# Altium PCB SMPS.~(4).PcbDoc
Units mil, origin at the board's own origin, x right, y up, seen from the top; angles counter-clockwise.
Board outline 2362.21 x 3149.61 mil, 2 copper layers (Top Layer, Bottom Layer); 139 components, 61 nets, 421 pads, 34 vias.
Unrouted connection lines stored in the file: 287.
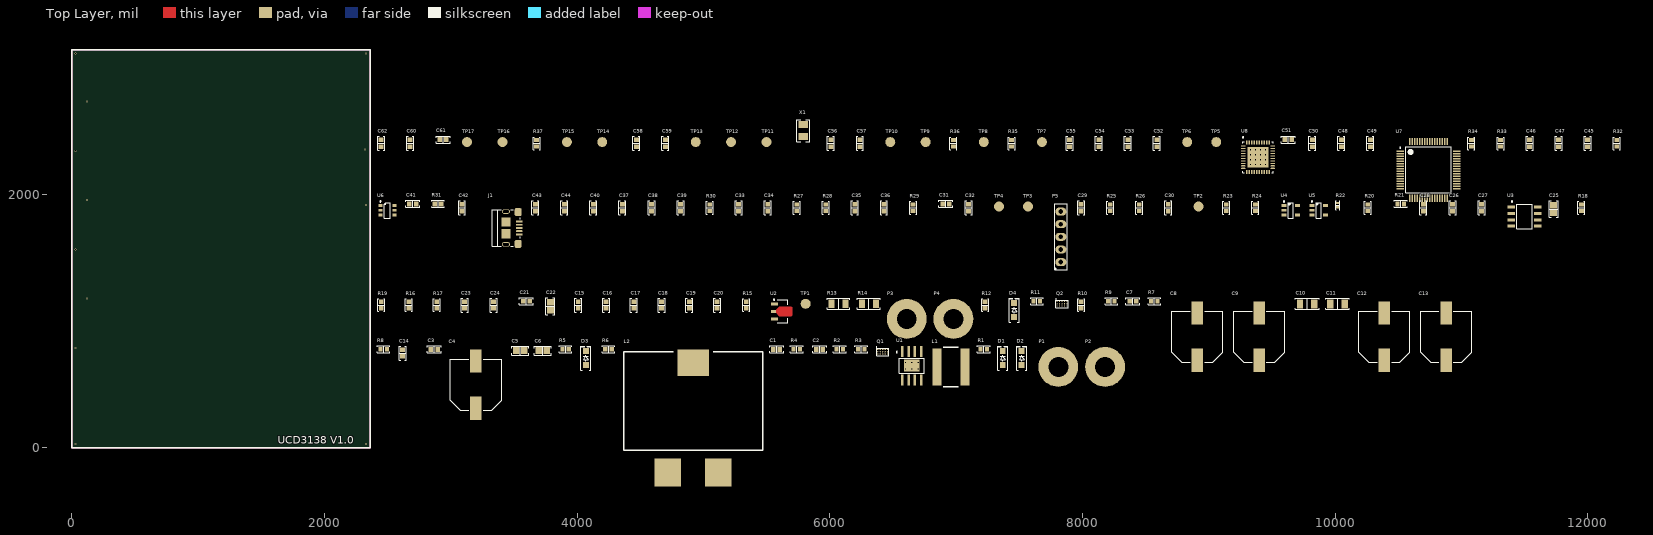
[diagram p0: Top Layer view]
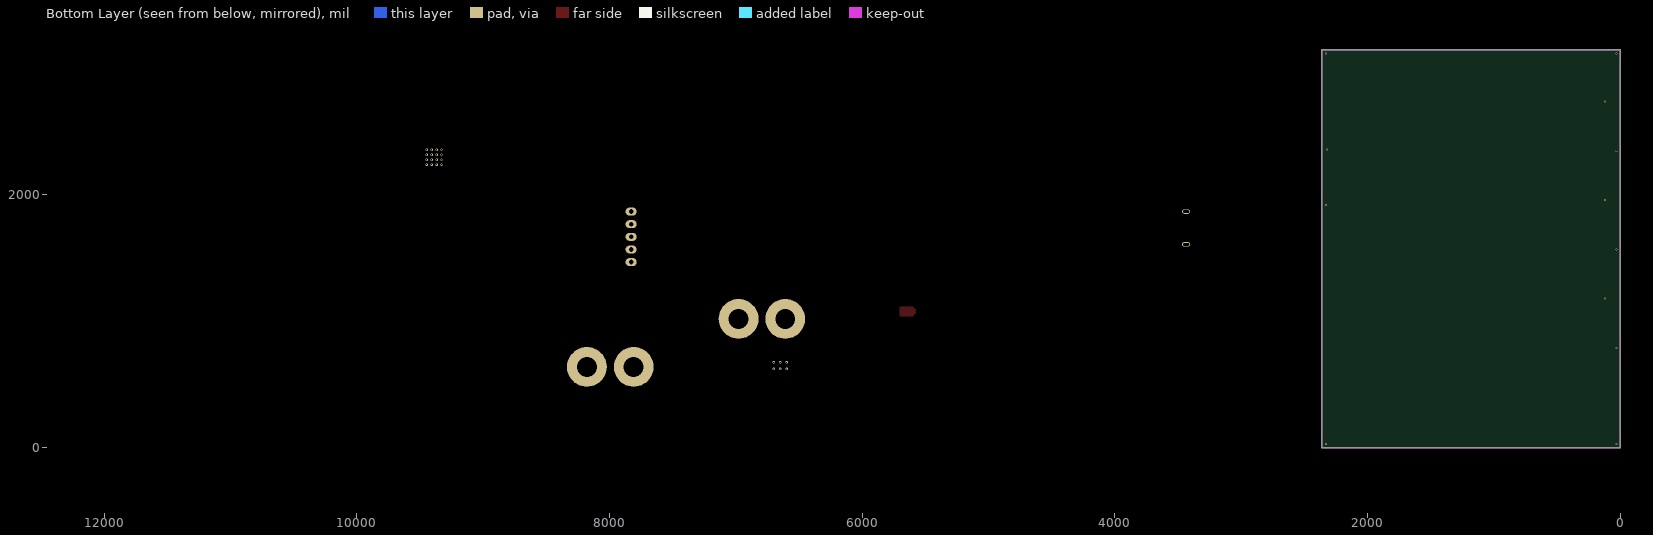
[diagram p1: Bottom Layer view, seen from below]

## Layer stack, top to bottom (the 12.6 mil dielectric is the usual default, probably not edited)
Top Solder: solder mask 0.4, Solder Resist, Dk 3.5
Top Layer: signal copper 1.4
Dielectric 1: dielectric 12.6, FR-4, Dk 4.8
Bottom Layer: signal copper 1.4
Bottom Solder: solder mask 0.4, Solder Resist, Dk 3.5

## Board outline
0,0 0,3149.61 2362.2,3149.61 2362.2,0

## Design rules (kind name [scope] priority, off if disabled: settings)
Clearance [All] p1: gap=10 ignorepadtopadclearanceinfootprint=FALSE except(0: Arc-Hole Track-Hole SMDPad-Hole THPad-Hole Via-Hole Fill-Hole Poly-Hole Region-Hole Text-Hole; 7: SMDPad-SMDPad; 8: Track-SMDPad; 9: Arc-Arc Arc-Track Arc-SMDPad Track-Track; 20: THPad-THPad)
ComponentClearance U1 [InComponent('U1')] p1: gap=20 collisioncheckmode=3 verticalgap=0 showdistances=TRUE
ComponentClearance [All] p2: gap=19.68 collisioncheckmode=3 verticalgap=3.94 showdistances=TRUE
Height [All] p1: minheight=0 maxheight=2000 prefheight=500
HoleSize [All] p1: absolutevalues=TRUE maxlimit=393.7 minlimit=7.87 maxpercent=80.000 minpercent=20.000
MinimumSolderMaskSliver [All] p1: minsoldermaskwidth=1
PlaneClearance [All] p1: clearance=10
PlaneConnect [All] p1: planeconnectstyle=Direct reliefexpansion=20 reliefentries=4 reliefconductorwidth=20 reliefairgap=20
PolygonConnect GND [InNet('GND')] p1: connectstyle=Direct reliefconductorwidth=10 reliefentries=4 polygonreliefangle="90 Angle" airgapwidth=10
PolygonConnect DirectConnect [All] p2: connectstyle=Direct reliefconductorwidth=10 reliefentries=4 polygonreliefangle="90 Angle" airgapwidth=10
RoutingVias [All] p1: holewidth=7.87 width=31.5 viastyle="Through Hole" minholewidth=7.87 minwidth=15.75 maxholewidth=15.75 maxwidth=31.5
SilkToSilkClearance [All] p1: silktosilkclearance=0
SolderMaskExpansion [All] p1: expansion=4
Width [All] p1: maxlimit=500 minlimit=10 preferedwidth=10
23 further rules are at their usual default settings.

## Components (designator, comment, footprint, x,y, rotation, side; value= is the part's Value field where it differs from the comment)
C1 "10nF" C0603 5578.9,778.9 r0 top
C2 "1nF" C0603 5918.9,778.9 r0 top
C3 "10nF" C0603 2868.9,778.9 r0 top
C4 "47µF 80V" "CAP ALUM 10.3MM" 3198.9,498.9 r90 top
C5 "10µF 16V" C0805 3548.9,768.9 r0 top
C6 "10µF 16V" C0805 3728.9,768.9 r0 top
C7 "10nF" C0603 8398.9,1158.9 r0 top
C8 "47µF 80V" "CAP ALUM 10.3MM" 8908.9,878.9 r90 top
C9 "47µF 80V" "CAP ALUM 10.3MM" 9398.9,878.9 r90 top
C10 "1µF 80V" C1206 9778.9,1138.9 r0 top
C11 "1µF 80V" C1206 10018.9,1138.9 r0 top
C12 "47µF 80V" "CAP ALUM 10.3MM" 10388.9,878.9 r90 top
C13 "47µF 80V" "CAP ALUM 10.3MM" 10878.9,878.9 r90 top
C14 "47pF" C0603 2618.9,748.9 r90 top
C15 "10µF" C0603 4008.9,1128.9 r90 top
C16 "100nF" C0603 4228.9,1128.9 r90 top
C17 "10nF" C0603 4448.9,1128.9 r90 top
C18 "10µF" C0603 4668.9,1128.9 r90 top
C19 "100nF" C0603 4888.9,1128.9 r90 top
C20 "10nF" C0603 5108.9,1128.9 r90 top
C21 "100nF 16V" C0603 3598.9,1158.9 r0 top
C22 "1µF 16V" C0805 3788.9,1118.9 r90 top
C23 "22pF" C0603 3108.9,1128.9 r90 top
C24 "22pF" C0603 3338.9,1128.9 r90 top
C25 "10µF 16V" C0805 11728.9,1888.9 r90 top
C26 "33pF" C0603 10928.9,1898.9 r90 top
C27 "33pF" C0603 11158.9,1898.9 r90 top
C28 "1µF 16V" C0603 10698.9,1898.9 r90 top
C29 "22pF" C0603 7988.9,1898.9 r90 top
C30 "22pF" C0603 8678.9,1898.9 r90 top
C31 "1µF" C0603 6918.9,1928.9 r0 top
C32 "1µF" C0603 7098.9,1898.9 r90 top
C33 "100nF" C0603 5278.9,1898.9 r90 top
C34 "22pF" C0603 5508.9,1898.9 r90 top
C35 "22pF" C0603 6198.9,1898.9 r90 top
C36 "100nF" C0603 6428.9,1898.9 r90 top
C37 "4.7µF" C0603 4358.9,1898.9 r90 top
C38 "4.7µF" C0603 4588.9,1898.9 r90 top
C39 "4.7µF" C0603 4818.9,1898.9 r90 top
C40 "47pF" C0603 4128.9,1898.9 r90 top
C41 "10nF" C0603 2698.9,1928.9 r0 top
C42 "10nF" C0603 3088.9,1898.9 r90 top
C43 "100nF" C0603 3668.9,1898.9 r90 top
C44 "100nF" C0603 3898.9,1898.9 r90 top
C45 "1µF" C0603 11998.9,2408.9 r90 top
C46 "10nF" C0603 11538.9,2408.9 r90 top
C47 "100nF" C0603 11768.9,2408.9 r90 top
C48 "2.2µF" C0603 10048.9,2408.9 r90 top
C49 "10nF" C0603 10278.9,2408.9 r90 top
C50 "47pF" C0603 9818.9,2408.9 r90 top
C51 "100nF" C0603 9628.9,2438.9 r0 top
C52 "1nF" C0603 8588.9,2408.9 r90 top
C53 "100nF" C0603 8358.9,2408.9 r90 top
C54 "1nF" C0603 8128.9,2408.9 r90 top
C55 "100nF" C0603 7898.9,2408.9 r90 top
C56 "33pF" C0603 6008.9,2408.9 r90 top
C57 "33pF" C0603 6238.9,2408.9 r90 top
C58 "26pF" C0603 4468.9,2408.9 r90 top
C59 "26pF" C0603 4698.9,2408.9 r90 top
C60 "2.2µF" C0603 2678.9,2408.9 r90 top
C61 "1µF" C0603 2938.9,2438.9 r0 top
C62 "1µF" C0603 2448.9,2408.9 r90 top
D1 "DSS120UTR" SOD123F 7368.9,708.9 r90 top
D2 "DSS120UTR" SOD123F 7518.9,708.9 r90 top
D3 "DSS120UTR" SOD123F 4068.9,708.9 r90 top
D4 "DSS120UTR" SOD123F 7458.9,1088.9 r90 top
J1 "10118192-0001LF" "FCI USB 10118193-0001LF" 3438.9,1738.9 r90 top
L1 "NR8040T220M" SELF_SMD_8x8 6958.9,638.9 r0 top
L2 "PQ2617BHA-220K" SELF_SMD_PQ2617 4918.9,368.9 r0 top
P1 "PTH" HOLE_4 7808.9,638.9 r0 top
P2 "PTH" HOLE_4 8178.9,638.9 r0 top
P3 "PTH" HOLE_4 6608.9,1018.9 r0 top
P4 "PTH" HOLE_4 6978.9,1018.9 r0 top
P5 "5x2.54" "SAMTEC SSW-105-03-T-S" 7828.9,1668.9 r90 top
Q1 "EPC2045" EPC2045 6418.9,758.9 r0 top
Q2 "EPC2045" EPC2045 7838.9,1138.9 r0 top
R1 "5R11" R0603 7218.9,778.9 r0 top
R2 "21.5k 0.1%" R0603 6078.9,778.9 r0 top
R3 "21.5k 0.1%" R0603 6248.9,778.9 r0 top
R4 "249k" R0603 5738.9,778.9 r0 top
R5 "10k" R0603 3908.9,778.9 r0 top
R6 "91k" R0603 4248.9,778.9 r0 top
R7 "1k 0.1%" R0603 8568.9,1158.9 r0 top
R8 "1k 0.1%" R0603 2468.9,778.9 r0 top
R9 "5R11" R0603 8228.9,1158.9 r0 top
R10 "30.1k" R0603 7988.9,1128.9 r90 top
R11 "10k" R0603 7638.9,1158.9 r0 top
R12 "10k" R0603 7228.9,1128.9 r90 top
R13 "1m 1% 1W 50ppm" R1206 6068.9,1138.9 r0 top
R14 "1m 1% 1W 50ppm" R1206 6308.9,1138.9 r0 top
R15 "1R" R0603 5338.9,1128.9 r90 top
R16 "1k" R0603 2668.9,1128.9 r90 top
R17 "1k" R0603 2888.9,1128.9 r90 top
R18 "301k 0.1%" R0603 11948.9,1898.9 r90 top
R19 "301k 0.1%" R0603 2448.9,1128.9 r90 top
R20 "1k 0.1%" R0603 10258.9,1898.9 r90 top
R21 "1k 0.1%" R0603 10518.9,1928.9 r0 top
R22 "10k CTN" "NTC 0402/1005" 10018.9,1918.9 r90 top
R23 "1k" R0603 9138.9,1898.9 r90 top
R24 "1k" R0603 9368.9,1898.9 r90 top
R25 "1k 0.1%" R0603 8218.9,1898.9 r90 top
R26 "1k 0.1%" R0603 8448.9,1898.9 r90 top
R27 "301k 0.1%" R0603 5738.9,1898.9 r90 top
R28 "301k 0.1%" R0603 5968.9,1898.9 r90 top
R29 "10k" R0603 6658.9,1898.9 r90 top
R30 "27R" R0603 5048.9,1898.9 r90 top
R31 "1R" R0603 2898.9,1928.9 r0 top
R32 "10k" R0603 12228.9,2408.9 r90 top
R33 "1M" R0603 11308.9,2408.9 r90 top
R34 "27R" R0603 11078.9,2408.9 r90 top
R35 "100" R0603 7438.9,2408.9 r90 top
R36 "100" R0603 6978.9,2408.9 r90 top
R37 "2.2k" R0603 3678.9,2408.9 r90 top
TP1 "Test Point" "Test Point" 5808.9,1138.9 r0 top
TP2 "Test Point" "Test Point" 8918.9,1908.9 r0 top
TP3 "Test Point" "Test Point" 7568.9,1908.9 r0 top
TP4 "Test Point" "Test Point" 7338.9,1908.9 r0 top
TP5 "Test Point" "Test Point" 9058.9,2418.9 r0 top
TP6 "Test Point" "Test Point" 8828.9,2418.9 r0 top
TP7 "Test Point" "Test Point" 7678.9,2418.9 r0 top
TP8 "Test Point" "Test Point" 7218.9,2418.9 r0 top
TP9 "Test Point" "Test Point" 6758.9,2418.9 r0 top
TP10 "Test Point" "Test Point" 6478.9,2418.9 r90 top
TP11 "Test Point" "Test Point" 5498.9,2418.9 r90 top
TP12 "Test Point" "Test Point" 5218.9,2418.9 r90 top
TP13 "Test Point" "Test Point" 4938.9,2418.9 r90 top
TP14 "Test Point" "Test Point" 4198.9,2418.9 r90 top
TP15 "Test Point" "Test Point" 3918.9,2418.9 r90 top
TP16 "Test Point" "Test Point" 3408.9,2418.9 r90 top
TP17 "Test Point" "Test Point" 3128.9,2418.9 r90 top
U1 "LM5164" R-PDSO-G8 6648.9,648.9 r0 top
U2 "AP7381-33Y-13" "ON SEMI SOT-89 H" 5618.9,1078.9 r0 top
U3 "MIC4605-1YM" SOIC-8 11498.9,1828.9 r0 top
U4 "LMV793" "TI SOT-23-5 DBV" 9648.9,1878.9 r0 top
U5 "LMV793" "TI SOT-23-5 DBV" 9868.9,1878.9 r0 top
U6 "IP4234CZ6" "VISHAY TSOP-6 MO-193C" 2498.9,1878.9 r0 top
U7 "ATSAME51J20A" TQFP-64N 10738.9,2198.9 r0 top
U8 "UCD3138RHAR" S-PVQFN-N40 9388.9,2298.9 r0 top
X1 "32.768kHz" "ABRACON ABS07" 5790,2510 r90 top

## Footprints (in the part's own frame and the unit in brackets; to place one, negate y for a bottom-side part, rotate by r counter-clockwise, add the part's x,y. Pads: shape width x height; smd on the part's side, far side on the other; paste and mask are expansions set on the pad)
"ABRACON ABS07" [mm] "Crystal, 2-Leads, Body 3.20x1.50mm, IPC Medium Density"
  rect 1.4x1.9 smd: 1(-1.2,0) 2(1.2,0)
  silkscreen extent -2.2,-1.3 2.2,1.3, body extent -1.62,-0.77 1.63,0.78, height 0.9
C0603 [mm] "Chip Capacitor, 2-Leads, Body 1.60x0.80mm, IPC Medium Density"
  rect 0.9x1 smd: 1(-0.675,0) 2(0.675,0)
  silkscreen extent -1.4,-0.7 1.4,0.7, body extent -0.8,-0.41 0.8,0.41, height 0.82
C0805 [mm] "Chip Capacitor, 2-Leads, Body 2.00x1.20mm, IPC Medium Density"
  rect 1.3x1.4 smd: 1(-0.8,0) 2(0.8,0)
  silkscreen extent -1.7,-0.9 1.7,0.9, body extent -1,-0.64 1,0.64, height 1.26
C1206 [mm] "Chip Capacitor, 2-Leads, Body 3.25x1.60mm, IPC Medium Density"
  rect 1.3x1.8 smd: 1(-1.45,0) 2(1.45,0)
  silkscreen extent -2.37,-1.12 2.37,1.12, body extent -1.6,-0.81 1.6,0.81, height 1.62
"CAP ALUM 10.3MM" [mm] "Aluminum Electrolytic Capacitor, Body 10.30x10.30x10.50mm, IPC Low Density"
  rect 4.65x2.3 smd: 1(-4.75,0) 2(4.75,0)
  silkscreen extent -5.15,-5.15 5.15,5.15, body extent -5.8,-5.15 5.8,5.15, height 10.5
EPC2045 [mm] "EPC2045 GaNFet"
  round 0.23 smd: 1(-1,0.45) 2(-1,0) 3(-1,-0.45) 4(-0.5,0.45) 5(-0.5,0) 6(-0.5,-0.45) 7(0,0.45) 8(0,0) 9(0,-0.45) 10(0.5,0.45) 11(0.5,0) 12(0.5,-0.45) 13(1,0.45) 14(1,0) 15(1,-0.45)
  silkscreen extent -1.3,-0.75 1.25,1.05, body extent -1.25,-0.75 1.25,0.75, height 0.68
"FCI USB 10118193-0001LF" [mm] "USB 2.0 Type B Micro"
  oval 0.4x1.35 smd: 1(1.3,-2.625) 2(0.65,-2.625) 3(0,-2.625) 4(-0.65,-2.625) 5(-1.3,-2.625)
  oval 0.9x1.6 hole 0.5 slot 1.2 at 90 deg: S(-3.3,0.05) S(3.3,0.05)
  rrect50% 1.6x1.4 smd: S(-3.2,-2.4) S(3.2,-2.4)
  rect 1.9x1.8 smd: S(-1.2,0.05) S(1.2,0.05)
  silkscreen extent -3.7,-2.8 3.7,2.8, body extent -3.93,-2.9 3.93,2.76, height 2.78
HOLE_4 [mm] "Hole for M4 screw"
  round 8 hole 4: 1(0,0)
"NTC 0402/1005" [mm] "Chip Thermistor, 2-Leads, Body 1.00x0.50mm, IPC Medium Density"
  rect 0.5x0.55 smd: 1(-0.45,0) 2(0.45,0)
  silkscreen extent -0.9,-0.4 0.9,0.4, body extent -0.5,-0.26 0.5,0.26, height 0.52
"ON SEMI SOT-89 H" [mm] "SOT89, 3-Leads, Body 4.50x2.50mm, Pitch 1.50mm, Lead Span 3.3mm, IPC Medium Density"
  rect 1.4x0.6 smd: 1(-1.4,1.5) 3(-1.4,-1.5)
  rect 1x0.6 smd: 2(-1.6,0)
  Top Layer region: -1.1,0.3 -0.45,0.95 1.975,0.95 2.1,0.825 2.1,-0.825 1.975,-0.95 -0.45,-0.95 -1.1,-0.3
  silkscreen extent -1.65,-2.3 1.25,2.47, body extent -2.05,-2.25 2.1,2.25, height 1.5
R0603 [mm] "Chip Resistor, 2-Leads, Body 1.60x0.80mm, IPC Medium Density"
  rect 0.85x0.95 smd: 1(-0.65,0) 2(0.65,0)
  silkscreen extent -1.27,-0.7 1.27,0.7, body extent -0.8,-0.4 0.8,0.4, height 0.45
R1206 [mm] "Chip Resistor, 2-Leads, Body 3.13x1.55mm, IPC Medium Density"
  rect 1.2x1.65 smd: 1(-1.4,0) 2(1.4,0)
  silkscreen extent -2.3,-1.1 2.3,1.1, body extent -1.57,-0.8 1.62,0.8, height 0.6
R-PDSO-G8 [mm] "SOIC, 8-Leads, Body 4,90x3,90mm, Pitch 1,27mm, Thermal Pad 3,10x2,40mm, IPC Medium Density"
  rect 0.5x2.2 smd: 1(-1.905,2.875) 2(-0.635,2.875) 3(0.635,2.875) 4(1.905,2.875) 5(1.905,-2.875) 6(0.635,-2.875) 7(-0.635,-2.875) 8(-1.905,-2.875)
  rect 3.1x2.4 smd paste+0: 9(0,0)
  silkscreen extent -3.12,-1.52 2.5,2.87, body extent -2.5,-2 2.5,2, height 1.7
S-PVQFN-N40 [mm] "VQFN, 40-Leads, Body 6,00x6,00mm, Pitch 0,50mm, Thermal Pad 4,92x4,92mm, IPC Medium Density"
  oval 0.85x0.28 smd: 1(-2.975,2.25) 2(-2.975,1.75) 3(-2.975,1.25) 4(-2.975,0.75) 5(-2.975,0.25) 6(-2.975,-0.25) 7(-2.975,-0.75) 8(-2.975,-1.25) 9(-2.975,-1.75) 10(-2.975,-2.25) 21(2.975,-2.25) 22(2.975,-1.75) 23(2.975,-1.25) 24(2.975,-0.75) 25(2.975,-0.25) 26(2.975,0.25) 27(2.975,0.75) 28(2.975,1.25) 29(2.975,1.75) 30(2.975,2.25)
  oval 0.28x0.85 smd: 11(-2.25,-2.975) 12(-1.75,-2.975) 13(-1.25,-2.975) 14(-0.75,-2.975) 15(-0.25,-2.975) 16(0.25,-2.975) 17(0.75,-2.975) 18(1.25,-2.975) 19(1.75,-2.975) 20(2.25,-2.975) 31(2.25,2.975) 32(1.75,2.975) 33(1.25,2.975) 34(0.75,2.975) 35(0.25,2.975) 36(-0.25,2.975) 37(-0.75,2.975) 38(-1.25,2.975) 39(-1.75,2.975) 40(-2.25,2.975)
  rect 4.15x4.15 smd paste-2.075: 41(0,0)
  silkscreen extent -3.12,-3.08 3.08,4.12, body extent -3.08,-3.08 3.08,3.08, height 1
"SAMTEC SSW-105-03-T-S" [mm]
  oval 1.6x2.25 hole 0.95: 1(-5.08,0) 2(-2.54,0) 3(0,0) 4(2.54,0) 5(5.08,0)
  silkscreen extent -6.61,-1.27 6.61,1.27, body extent -6.6,-1.21 6.6,1.21, height 8.51
SELF_SMD_8x8 [mm] "Self SMD 8x8mm"
  rect 1.8x7.5 smd: 1(-2.8,0) 2(2.8,0)
  silkscreen extent -1.5,-4 1.5,4, body extent -4,-4 4,4, height 3
SELF_SMD_PQ2617 [mil] "Bourns shielded power inductor PQ2617"
  rect 210x220 smd: 1(-200,-565) 2(200,-565)
  rect 250x208 smd: 3(0,304)
  silkscreen extent -549,-390 549,390, body extent -549,-433 549,433, height 748
SOD123F [mm] "SODFL, 2-Leads, Body 1.60x3.50mm, IPC Medium Density"
  rect 1.2x1.2 smd: 1(-1.43,0) 2(1.43,0)
  silkscreen extent -2.41,-1.02 2.41,1.02, body extent -1.75,-0.8 1.75,0.8, height 1.1
SOIC-8 [mm] "8-Pin Plastic Narrow Body Small Outline Integrated Circuit 1.27 mm Pitch, IPC Medium Density"
  rect 1.5x0.6 smd: 1(-2.7,1.905) 2(-2.7,0.635) 3(-2.7,-0.635) 4(-2.7,-1.905) 5(2.7,-1.905) 6(2.7,-0.635) 7(2.7,0.635) 8(2.7,1.905)
  silkscreen extent -2.66,-2.45 1.52,3.17, body extent -1.95,-2.45 1.95,2.45, height 1.76
"Test Point" [mm] "Test Point"
  round 2 smd: 1(0,0)
"TI SOT-23-5 DBV" [mm] "SOT23, 5-Leads, Body 2.90x2.80mm, Pitch 0.95mm, IPC Medium Density"
  rect 1x0.55 smd: 1(-1.35,0.95) 2(-1.35,0) 3(-1.35,-0.95) 4(1.35,-0.95) 5(1.35,0.95)
  silkscreen extent -1.47,-1.55 0.5,1.9, body extent -1.44,-1.43 1.39,1.48, height 1.5
TQFP-64N [mm] "TSQFP, 64-Leads, Body 10,00x10,00mm, Pitch 0,50mm, IPC Medium Density"
  rect 1.5x0.3 smd: 1(-5.7,3.75) 2(-5.7,3.25) 3(-5.7,2.75) 4(-5.7,2.25) 5(-5.7,1.75) 6(-5.7,1.25) 7(-5.7,0.75) 8(-5.7,0.25) 9(-5.7,-0.25) 10(-5.7,-0.75) 11(-5.7,-1.25) 12(-5.7,-1.75) 13(-5.7,-2.25) 14(-5.7,-2.75) 15(-5.7,-3.25) 16(-5.7,-3.75) 33(5.7,-3.75) 34(5.7,-3.25) 35(5.7,-2.75) 36(5.7,-2.25) 37(5.7,-1.75) 38(5.7,-1.25) 39(5.7,-0.75) 40(5.7,-0.25) 41(5.7,0.25) 42(5.7,0.75) 43(5.7,1.25) 44(5.7,1.75) 45(5.7,2.25) 46(5.7,2.75) 47(5.7,3.25) 48(5.7,3.75)
  rect 0.3x1.5 smd: 17(-3.75,-5.7) 18(-3.25,-5.7) 19(-2.75,-5.7) 20(-2.25,-5.7) 21(-1.75,-5.7) 22(-1.25,-5.7) 23(-0.75,-5.7) 24(-0.25,-5.7) 25(0.25,-5.7) 26(0.75,-5.7) 27(1.25,-5.7) 28(1.75,-5.7) 29(2.25,-5.7) 30(2.75,-5.7) 31(3.25,-5.7) 32(3.75,-5.7) 49(3.75,5.7) 50(3.25,5.7) 51(2.75,5.7) 52(2.25,5.7) 53(1.75,5.7) 54(1.25,5.7) 55(0.75,5.7) 56(0.25,5.7) 57(-0.25,5.7) 58(-0.75,5.7) 59(-1.25,5.7) 60(-1.75,5.7) 61(-2.25,5.7) 62(-2.75,5.7) 63(-3.25,5.7) 64(-3.75,5.7)
  silkscreen extent -5.82,-4.6 4.6,4.6, body extent -5,-5 5,5, height 1.2
"VISHAY TSOP-6 MO-193C" [mm] "SOT23, 6-Leads, Body 3.03x2.84mm, Pitch 0.95mm, IPC Medium Density"
  rect 0.85x0.55 smd: 1(-1.425,0.95) 2(-1.425,0) 3(-1.425,-0.95) 4(1.425,-0.95) 5(1.425,0) 6(1.425,0.95)
  silkscreen extent -1.55,-1.55 0.6,1.9, body extent -1.44,-1.52 1.44,1.53, height 1.45

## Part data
C1 C2 C3 C4 C5 C6 C7 C8 C9 C10 C11 C12 C13 C14 C15 C16 C17 C18 C19 C20 C21 C22 C23 C24 C25 C26 C27 C28 C29 C30 C31 C32 C33 C34 C35 C36 C37 C38 C39 C40 C41 C42 C43 C44 C45 C46 C47 C48 C49 C50 C51 C52 C53 C54 C55 C56 C57 C58 C59 C60 C61 C62: library part Cap, "Capacitor"
D1 D2 D3 D4: library part "D Schottky", "Schottky Diode"
J1: library part 1-353576-1, "USB 1.1, Right Angle, SMT, A Type, Receptacle, 4 Position, White"
L1 L2: library part "Inductor Iron", "Magnetic-Core Inductor"
P1 P2 P3 P4: "Plated Trough Hole for screew"
P5: library part "Header 5", "Header, 5-Pin"
Q1 Q2: library part MOSFET_N
R1 R2 R3 R4 R5 R6 R7 R8 R9 R10 R11 R12 R13 R14 R15 R16 R17 R18 R19 R20 R21 R23 R24 R25 R26 R27 R28 R29 R30 R31 R32 R33 R34 R35 R36 R37: library part Res2, "Resistor"
R22: library part "Res Varistor", "Varistor (Voltage-Sensitive Resistor)"
U1: "100-V Input, 1-A synchronous buck DC/DC converter with ultra-low IQ"
U2: library part "Volt Reg", "Voltage Regulator"
U3: "85V Half-Bridge MOSFET Driver with Adaptive Dead Time  and Shoot-Through Protection"
U4 U5: library part "AOP - 1"
U6: "Single USB 2.0 ESD protection to IEC 61000-4-2 level 4"
U8: "Highly Integrated Digital Controller for Isolated Power with 3 Feedback Loops and 8 DPWM Outputs, 40pins"
X1: library part XTAL, "Crystal Oscillator"

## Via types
v1: diameter 19.68, hole 7.87, Top Layer to Bottom Layer, 22 vias
v2: diameter 15.75, hole 7.87, Top Layer to Bottom Layer, 12 vias

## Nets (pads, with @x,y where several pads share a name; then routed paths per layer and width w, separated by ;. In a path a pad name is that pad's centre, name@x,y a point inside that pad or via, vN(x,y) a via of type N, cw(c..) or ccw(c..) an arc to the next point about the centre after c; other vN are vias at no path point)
+3.3V: C15.1 C16.1 C17.1 C38.1 C42.1 C43.2 C48.2 C51.2 C53.1 C55.2 C62.2 P5.1 R15.2 R31.1 R32.2 U2.1 U7.8 U7.21 U7.34 U7.48 U7.56 U8.27
+3.3Vana: C18.1 C19.1 C20.1 C33.1 C36.1 R15.1 R22.2 TP1.1 U4.5 U5.5
+12V: C2.2 C5.1 C6.1 C21.1 C22.1 C25.2 L1.2 R6.1 U3.1
+Vbus: C8.2 C9.2 C10.2 D1.1 L2.1 P1.1 R2.1
+Vcells: C11.2 C12.2 C13.2 D2.1 P2.1 Q1.3 R3.1
ALERT: TP9.1 U7.19 U8.19
Ccells: C28.1 L2.2 Q1.2 Q2.3 R5.2 TP3.1 U3.4
CTRL: TP10.1 U7.20 U8.20
DPWM0A: TP5.1 U3.5 U8.11
DPWM0B: TP6.1 U3.6 U8.12
GND: C4.1 C5.2 C6.2 C8.1 C9.1 C10.1 C11.1 C12.1 C13.1 C15.2 C16.2 C17.2 C18.2 C19.2 C20.2 C21.2 C22.2 C25.1 C26.1 C27.1 C31.1 C32.1 C33.2 C34.1 C35.1 C36.2 C37.1 C38.2 C39.2 C40.1 C41.1 C42.2 C43.1 C44.2 C45.1 C46.2 C47.1 C49.1 C50.1 C51.1 C52.2 C53.2 C54.2 C55.1 C56.2 C57.2 C58.1 C59.1 C60.2 C61.2 C62.1 J1.5 P5.5 Q2.2 R10.2 R11.2 R12.2 R13.1 R14.2 R25.1 R26.2 R27.2 R28.2 R29.2 R33.1 U1.1 U1.9 U2.2 U3.7 U4.2 U5.2 U7.7 U7.22 U7.33 U7.47 U7.54 U8.1 U8.6 U8.26 U8.29 U8.30 U8.32 U8.34 U8.36 U8.41
  other v1: 6597.72,623.31 6648.9,623.31 6700.08,623.31 6597.72,674.49 6648.9,674.49 6700.08,674.49 9329.84,2239.84 9369.21,2239.84 9408.58,2239.84 9447.95,2239.84 9329.84,2279.21 9369.21,2279.21 9408.58,2279.21 9447.95,2279.21 9329.84,2318.58 9369.21,2318.58 9408.58,2318.58 9447.95,2318.58 9329.84,2357.95 9369.21,2357.95 9408.58,2357.95 9447.95,2357.95
  other v2: 30,30 2330,30 30,790 120,1180 30,1570 2330,1920 120,1960 30,2350 2320,2360 120,2740 30,3120 2330,3120
Hcells: D3.2 R1.1 TP2.1 U3.3
Ibus_peak: C26.2 R16.2 TP13.1 U8.40
Ibus_sense: C31.2 R23.2 TP12.1 U8.39
Icells_peak: C27.2 R17.1 TP16.1 U8.3
Icells_sense: C32.2 R24.1 TP15.1 U8.4 U8.35
Lcells: D4.2 R9.1 TP4.1 U3.8
NetC1_1: C1.1 L1.1 R4.1 U1.8
NetC1_2: C1.2 U1.7
NetC2_1: C2.1 C14.2 R4.2
NetC4_2: C4.2 D1.2 D2.2 U1.2 U1.3
NetC14_1: C14.1 R6.2 R11.1 U1.5
NetC23_1: C23.1 R16.1 R18.2 R23.1 U4.1
NetC23_2: C23.2 C29.2 R18.1 R20.2 U4.4
NetC24_1: C24.1 C30.2 R19.2 R21.1 U5.4
NetC24_2: C24.2 R17.2 R19.1 R24.2 U5.1
NetC28_2: C28.2 U3.2
NetC29_1: C29.1 C34.2 R25.2 R27.1 U4.3
NetC30_1: C30.1 C35.2 R26.1 R28.1 U5.3
NetC37_2: C37.2 C41.2 R31.2 U8.37
NetC39_1: C39.1 C44.1 U7.53
NetC40_2: C40.2 R30.2 U6.6
NetC45_2: C45.2 C48.1 C49.2 U8.28
NetC46_1: C46.1 J1.S R33.2 U6.2
NetC50_2: C50.2 R34.2 U6.1
NetC56_1: C56.1 R35.1 U8.9
NetC57_1: C57.1 R36.1 U8.10
NetC58_2: C58.2 U7.31 X1.1
NetC59_2: C59.2 U7.32 X1.2
NetC60_1: C60.1 R37.1 U8.7
NetD3_1: D3.1 Q1.1 R1.2 R5.1
NetD4_1: D4.1 Q2.1 R9.2 R12.1
NetJ1_1: J1.1 U6.5
NetJ1_2: J1.2 U6.4
NetJ1_3: J1.3 U6.3
NetR10_1: R10.1 U1.4
R\S\T\: C47.2 P5.4 R32.1 U7.52
Rbus: C7.1 P3.1 R7.2 R13.2 R20.1
Rcells: C3.1 P4.1 R8.2 R14.1 R21.2
SCL: R35.2 TP7.1 U7.18
SDA: R36.2 TP8.1 U7.17
SMPS_R\E\S\E\T\: C61.1 R37.2 U7.16
SWCLK: U7.59
SWDCLK: P5.3
SWDIO: P5.2 U7.60
SYNC: U8.8
Temp: R22.1 R29.1 TP17.1 U8.2
"USB D+": R34.1 U7.46
"USB D-": R30.1 U7.45
Vbus_sense: C7.2 C52.1 R2.2 R7.1 TP11.1 U8.31 U8.38
Vcells_sense: C3.2 C54.1 R3.2 R8.1 TP14.1 U8.5 U8.33
pads on no net: J1.4 L2.3 Q1.4 Q1.5 Q1.6 Q1.7 Q1.8 Q1.9 Q1.10 Q1.11 Q1.12 Q1.13 Q1.14 Q1.15 Q2.4 Q2.5 Q2.6 Q2.7 Q2.8 Q2.9 Q2.10 Q2.11 Q2.12 Q2.13 Q2.14 Q2.15 U1.6 U2.3 U7.1 U7.2 U7.3 U7.4 U7.5 U7.6 U7.9 U7.10 U7.11 U7.12 U7.13 U7.14 U7.15 U7.23 U7.24 U7.25 U7.26 U7.27 U7.28 U7.29 U7.30 U7.35 U7.36 U7.37 U7.38 U7.39 U7.40 U7.41 U7.42 U7.43 U7.44 U7.49 U7.50 U7.51 U7.55 U7.57 U7.58 U7.61 U7.62 U7.63 U7.64 U8.13 U8.14 U8.15 U8.16 U8.17 U8.18 U8.21 U8.22 U8.23 U8.24 U8.25

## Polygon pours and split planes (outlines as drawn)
GND on Bottom Layer "GND_bottom" (solid, shelved, pour order 72): 0,0 2362.2,0 2362.2,3149.61 0,3149.61
GND on Top Layer "GND_top" (solid, shelved, pour order 73): 0,0 2362.2,0 2362.2,3149.61 0,3149.61

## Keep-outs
Keep-Out Layer:
  the board outline again, w10

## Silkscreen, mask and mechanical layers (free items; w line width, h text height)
Top Overlay:
  the board outline again, w10
  text "UCD3138 V1.0" at 1630,30 h60
Drill Drawing:
  the board outline again, w10

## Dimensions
0,-39.37 to 2362.2,-39.37 on Mechanical 2
-39.37,0 to -39.37,3149.61 on Mechanical 2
